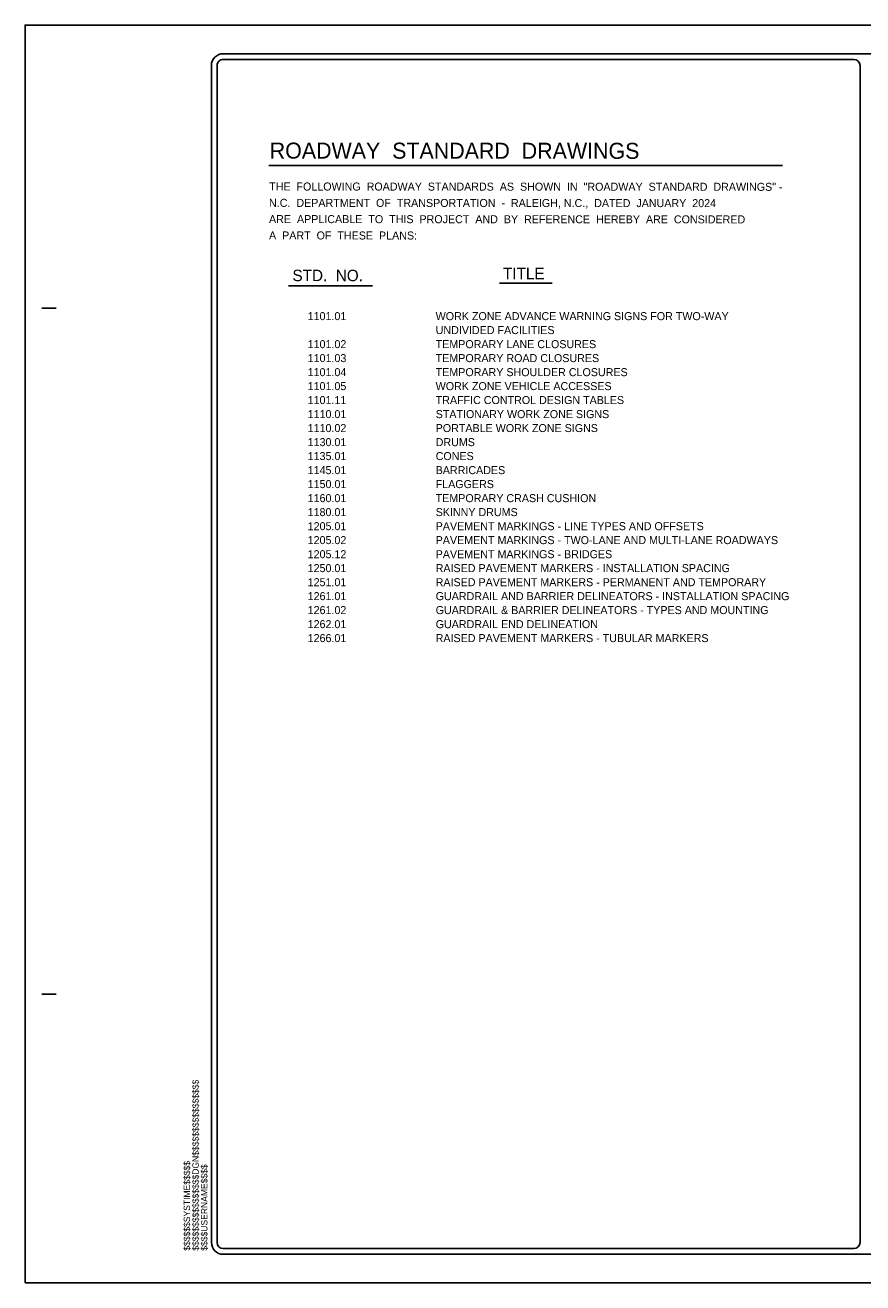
# Model space of a CAD drawing. Extents: x 0 to 1868, y 0 to 1100.
# Drawn here: x 0 to 733, y 0 to 1100 of the extents above; entities that cross this region are included whole.
import ezdxf

# ---------------------------------------------------------------- set-up
doc = ezdxf.new("R2010")
doc.units = 0
doc.layers.add('Exist Utilities Sanitary Sewer Test Hole SUE LOS A CELL', color=7, linetype='Continuous')
doc.layers.add('P_RDY_ROW_Permanent_Easement_CELL', color=7, linetype='Continuous')

msp = doc.modelspace()

# ---------------------------------------------------------------- linework, layer by layer
at = {"layer": 'Exist Utilities Sanitary Sewer Test Hole SUE LOS A CELL'}
msp.add_lwpolyline([(0, 0), (1688, 0), (1688, 1100), (0, 1100)], close=True, dxfattribs=at)
at = {"layer": 'P_RDY_ROW_Permanent_Easement_CELL'}
for p, q in [((1652.7, 1075), (173.3, 1075)), ((725.2, 1070), (173.3, 1070)), ((163, 1064.7), (163, 35.3)), ((168, 1064.7), (168, 35.3)), ((730.5, 1064.7), (730.5, 35.3)), ((213.3, 977.2), (662.7, 977.2)), ((230.5, 872), (303.9, 872)), ((244.6, 872), (244.6, 872)), ((244.6, 872), (244.6, 872)), ((415, 874.3), (461, 874.3)), ((14.5, 852.5), (27, 852.5)), ((14.5, 252.5), (27, 252.5)), ((163, 25), (163, 25)), ((173.3, 30), (725.2, 30)), ((173.3, 25), (1652.7, 25))]:
    msp.add_line(p, q, dxfattribs=at)
for centre, radius, start, end in [((173.3, 1064.7), 10.3, 89.9972, 180), ((173.3, 1064.7), 5.29, 89.9972, 180), ((725.2, 1064.7), 5.29, 0.0001, 89.9995), ((173.3, 35.3), 10.3, 180, 270), ((173.3, 35.3), 5.29, 180, 270), ((725.2, 35.3), 5.29, 270.0005, 359.9999)]:
    msp.add_arc(centre, radius, start, end, dxfattribs=at)

# ---------------------------------------------------------------- texts
for s, height, rotation, p in [('ROADWAY  STANDARD  DRAWINGS', 13.999, 359.9598, (214, 983.3)), ('THE  FOLLOWING  ROADWAY  STANDARDS  AS  SHOWN  IN  "ROADWAY  STANDARD  DRAWINGS" -', 7, 359.9598, (213.5, 955.4)), ('N.C.  DEPARTMENT  OF  TRANSPORTATION  -  RALEIGH, N.C.,  DATED  JANUARY  2024', 7, 359.9598, (213.4, 941.1)), ('ARE  APPLICABLE  TO  THIS  PROJECT  AND  BY  REFERENCE  HEREBY  ARE  CONSIDERED', 7, 359.9598, (213.4, 926.9)), ('A  PART  OF  THESE  PLANS:', 7, 359.9598, (213.4, 912.6)), ('STD.  NO.', 10, 359.9598, (233.9, 876.1)), ('TITLE', 10, 359.9598, (418.1, 877.8)), ('$$$$$$$$$$$$$$$$DGN$$$$$$$$$$$$$$$$', 5.584, 90, (151.9, 28.1)), ('$$$$$$SYSTIME$$$$$', 5.584, 90, (144.3, 28.1)), ('$$$$USERNAME$$$$', 5.584, 90, (159.5, 28.1))]:
    msp.add_text(s, height=height, rotation=rotation, dxfattribs=at).set_placement(p)
for s, p in [('1101.01         ', (247.2, 842)), ('WORK ZONE ADVANCE WARNING SIGNS FOR TWO-WAY', (359.2, 842)), ('UNDIVIDED FACILITIES', (359.2, 829.8)), ('1101.02        ', (247.2, 817.5)), ('TEMPORARY LANE CLOSURES', (359.2, 817.5)), ('1101.03         ', (247.2, 805.3)), ('TEMPORARY ROAD CLOSURES', (359.2, 805.3)), ('1101.04        ', (247.2, 793)), ('TEMPORARY SHOULDER CLOSURES', (359.2, 793)), ('1101.05        ', (247.2, 780.8)), ('WORK ZONE VEHICLE ACCESSES', (359.2, 780.8)), ('1101.11         ', (247.2, 768.6)), ('TRAFFIC CONTROL DESIGN TABLES', (359.2, 768.6)), ('1110.01         ', (247.2, 756.3)), ('STATIONARY WORK ZONE SIGNS', (359.2, 756.3)), ('1110.02         ', (247.2, 744.1)), ('PORTABLE WORK ZONE SIGNS', (359.2, 744.1)), ('1130.01         ', (247.2, 731.8)), ('DRUMS', (359.2, 731.8)), ('1135.01         ', (247.2, 719.6)), ('CONES', (359.2, 719.6)), ('1145.01         ', (247.2, 707.3)), ('BARRICADES', (359.2, 707.3)), ('1150.01         ', (247.2, 695.1)), ('FLAGGERS', (359.2, 695.1)), ('1160.01         ', (247.2, 682.8)), ('TEMPORARY CRASH CUSHION', (359.2, 682.8)), ('1180.01         ', (247.2, 670.6)), ('SKINNY DRUMS', (359.2, 670.6)), ('1205.01         ', (247.2, 658.3)), ('PAVEMENT MARKINGS - LINE TYPES AND OFFSETS', (359.2, 658.3)), ('1205.02         ', (247.2, 646.1)), ('PAVEMENT MARKINGS - TWO-LANE AND MULTI-LANE ROADWAYS', (359.2, 646.1)), ('1205.12         ', (247.2, 633.8)), ('PAVEMENT MARKINGS - BRIDGES', (359.2, 633.8)), ('1250.01         ', (247.2, 621.6)), ('RAISED PAVEMENT MARKERS - INSTALLATION SPACING', (359.2, 621.6)), ('1251.01         ', (247.2, 609.3)), ('RAISED PAVEMENT MARKERS - PERMANENT AND TEMPORARY ', (359.2, 609.3)), ('1261.01         ', (247.2, 597.1)), ('GUARDRAIL AND BARRIER DELINEATORS - INSTALLATION SPACING', (359.2, 597.1)), ('1261.02         ', (247.2, 584.9)), ('GUARDRAIL & BARRIER DELINEATORS - TYPES AND MOUNTING ', (359.2, 584.9)), ('1262.01         ', (247.2, 572.6)), ('GUARDRAIL END DELINEATION', (359.2, 572.6)), ('1266.01         ', (247.2, 560.4)), ('RAISED PAVEMENT MARKERS - TUBULAR MARKERS', (359.2, 560.4))]:
    msp.add_text(s, height=7, dxfattribs=at).set_placement(p)

doc.saveas('drawing.dxf')
